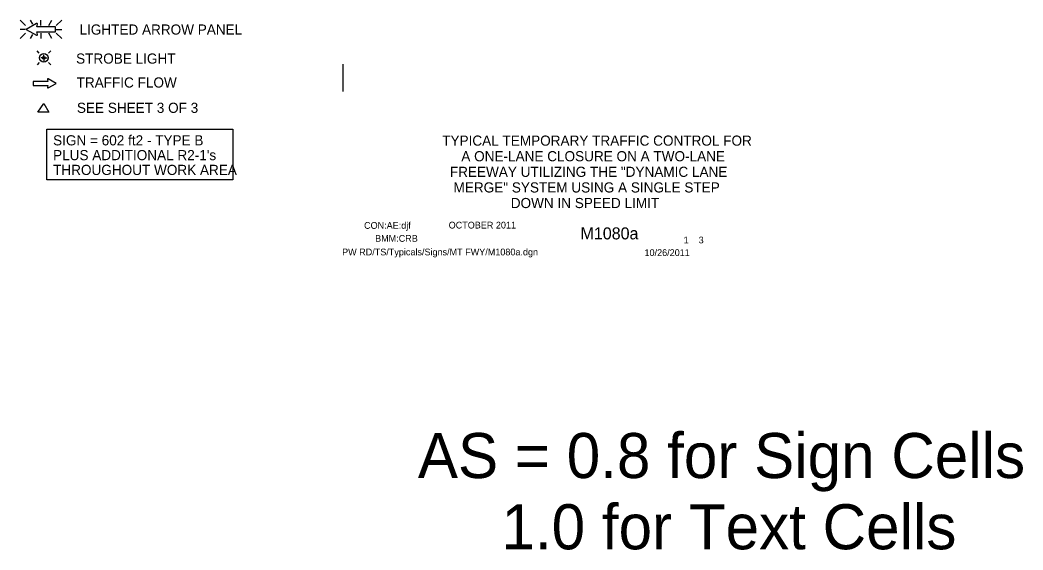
# Model space of a CAD drawing. Extents: x 15277 to 18126, y 1908 to 6555.
# Drawn here: x 15295 to 16214, y 1908 to 2394 of the extents above; entities that cross this region are included whole.
import ezdxf

# ---------------------------------------------------------------- set-up
doc = ezdxf.new("R2010")
doc.units = 0
for name, color, linetype in [('ALI_LEGAL_EX', 7, 'Continuous'), ('BORDER_SIGNAL_WO', 7, 'Continuous'), ('MT_SCRATCH_LEVEL_E', 7, 'Continuous'), ('TRAFFIC_SIGNS_PR', 7, 'Continuous'), ('TYPICAL_TEXT_DIMEN_EX', 7, 'Continuous'), ('TYPICAL_TEXT_DIMEN_PR', 7, 'Continuous')]:
    doc.layers.add(name, color=color, linetype=linetype)

msp = doc.modelspace()

# ---------------------------------------------------------------- linework, layer by layer
at = {"layer": 'ALI_LEGAL_EX'}
msp.add_lwpolyline([(15590.81, 2328.27), (15590.81, 2353.27)], dxfattribs=at)
at = {"layer": 'MT_SCRATCH_LEVEL_E'}
for p, q in [((15319.91, 2337.49), (15306.65, 2337.49)), ((15306.65, 2337.49), (15306.65, 2333.75)), ((15319.59, 2339.27), (15319.91, 2337.49)), ((15327.52, 2335.64), (15320.28, 2339.75)), ((15306.65, 2333.75), (15319.91, 2333.75)), ((15319.91, 2333.75), (15319.59, 2331.97)), ((15320.28, 2331.49), (15327.52, 2335.64))]:
    msp.add_line(p, q, dxfattribs=at)
for centre, start, end in [((15320.05, 2339.34), 60.42484, 189.96381), ((15320.05, 2331.9), 170.03619, 299.77312)]:
    msp.add_arc(centre, 0.463, start, end, dxfattribs=at)
at = {"layer": 'TRAFFIC_SIGNS_PR'}
for p, q in [((15294.52, 2393.66), (15299.45, 2388.73)), ((15306.28, 2389.84), (15304.08, 2393.67)), ((15313.6, 2388.73), (15313.6, 2393.67)), ((15320.84, 2388.73), (15323.69, 2393.67)), ((15327.75, 2388.73), (15332.69, 2393.67)), ((15299.45, 2385.18), (15294.52, 2385.18)), ((15327.75, 2385.18), (15332.69, 2385.18)), ((15294.52, 2376.69), (15299.45, 2381.62)), ((15304.03, 2376.68), (15306.14, 2380.35)), ((15313.6, 2381.62), (15313.6, 2376.68)), ((15323.73, 2376.68), (15320.88, 2381.62)), ((15327.75, 2381.62), (15332.69, 2376.68)), ((15312.11, 2363.34), (15310.08, 2365.37)), ((15320.67, 2363.33), (15322.71, 2365.37)), ((15316.39, 2359.05), (15313.51, 2359.05)), ((15316.39, 2359.05), (15316.39, 2361.93)), ((15316.39, 2359.05), (15316.39, 2355.12)), ((15316.39, 2359.05), (15319.27, 2359.05)), ((15312.11, 2354.77), (15310.08, 2352.74)), ((15322.7, 2352.74), (15320.67, 2354.77))]:
    msp.add_line(p, q, dxfattribs=at)
for points in [[(15309.53, 2390.45), (15300.24, 2385.18), (15309.53, 2379.85)], [(15310.41, 2380.48), (15310, 2382.75), (15327.02, 2382.75), (15327.02, 2387.55), (15310, 2387.55), (15310.41, 2389.83)]]:
    msp.add_lwpolyline(points, dxfattribs=at)
for radius in [3.94, 1.28]:
    msp.add_circle((15316.39, 2359.05), radius, dxfattribs=at)
for centre, radius, start, end in [((15309.82, 2389.93), 0.598, 350.73078, 118.89165), ((15309.82, 2380.38), 0.597, 241.48329, 9.95933)]:
    msp.add_arc(centre, radius, start, end, dxfattribs=at)
at = {"layer": 'TYPICAL_TEXT_DIMEN_EX'}
msp.add_lwpolyline([(15319.21, 2293.77), (15489.58, 2293.77), (15489.58, 2247.2), (15319.21, 2247.2)], close=True, dxfattribs=at)
at = {"layer": 'TYPICAL_TEXT_DIMEN_PR'}
msp.add_lwpolyline([(15310.85, 2309.26), (15316.31, 2317.13), (15320.94, 2309.26)], close=True, dxfattribs=at)

# ---------------------------------------------------------------- texts
at = {"layer": 'BORDER_SIGNAL_WO'}
for s, height, p in [('TYPICAL TEMPORARY TRAFFIC CONTROL FOR', 9.3, (15681.73, 2278.54)), ('A ONE-LANE CLOSURE ON A TWO-LANE', 9.3, (15699.24, 2264.24)), ('FREEWAY UTILIZING THE "DYNAMIC LANE', 9.3, (15688.74, 2249.94)), ('MERGE" SYSTEM USING A SINGLE STEP ', 9.3, (15692.1, 2235.64)), ('DOWN IN SPEED LIMIT', 9.3, (15744.6, 2221.34)), ('CON:AE:djf  ', 6.2, (15610.05, 2202.35)), ('    OCTOBER 2011    ', 6.2, (15678.44, 2202.63)), ('    M1080a   ', 11, (15792.22, 2192.67)), ('BMM:CRB   ', 6.2, (15620.17, 2190.46)), (' 1    3 ', 6.2, (15900.81, 2188.99)), ('PW RD/TS/Typicals/Signs/MT FWY/M1080a.dgn      ', 6.2, (15589.92, 2178)), ('10/26/2011    ', 6.2, (15867.29, 2177.42)), ('AS = 0.8 for Sign Cells', 41.2877, (15659.37, 1973.92)), ('     1.0 for Text Cells', 41.2877, (15659.37, 1908.64))]:
    msp.add_text(s, height=height, dxfattribs=at).set_placement(p)
at = {"layer": 'TYPICAL_TEXT_DIMEN_EX'}
for s, p in [('LIGHTED ARROW PANEL', (15349.03, 2380.35)), ('STROBE LIGHT', (15345.92, 2353.74)), ('TRAFFIC FLOW', (15346.38, 2331.81)), ('SEE SHEET 3 OF 3', (15346.67, 2308.61)), ('SIGN = 602 ft2 - TYPE B', (15324.82, 2278.8)), ("PLUS ADDITIONAL R2-1's", (15324.82, 2265.25)), ('THROUGHOUT WORK AREA', (15324.82, 2251.7))]:
    msp.add_text(s, height=9.3, dxfattribs=at).set_placement(p)

doc.saveas('drawing.dxf')
